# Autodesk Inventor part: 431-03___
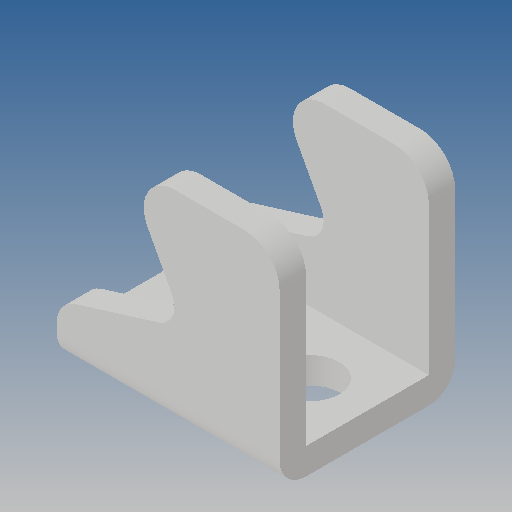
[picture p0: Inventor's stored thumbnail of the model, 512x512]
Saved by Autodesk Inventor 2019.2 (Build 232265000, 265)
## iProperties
Created: 2010-06
Part Number: 431-03___
Material: Ogólny
Document SubType Name: Modeling
Designer: CADENGINEERING4
Density: 1 g/cm^3
Appearance: Domyślna
Author: CADENGINEERING4
Revision Number: ANY
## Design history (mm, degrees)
feature "NONE"
node "Bryła1"
